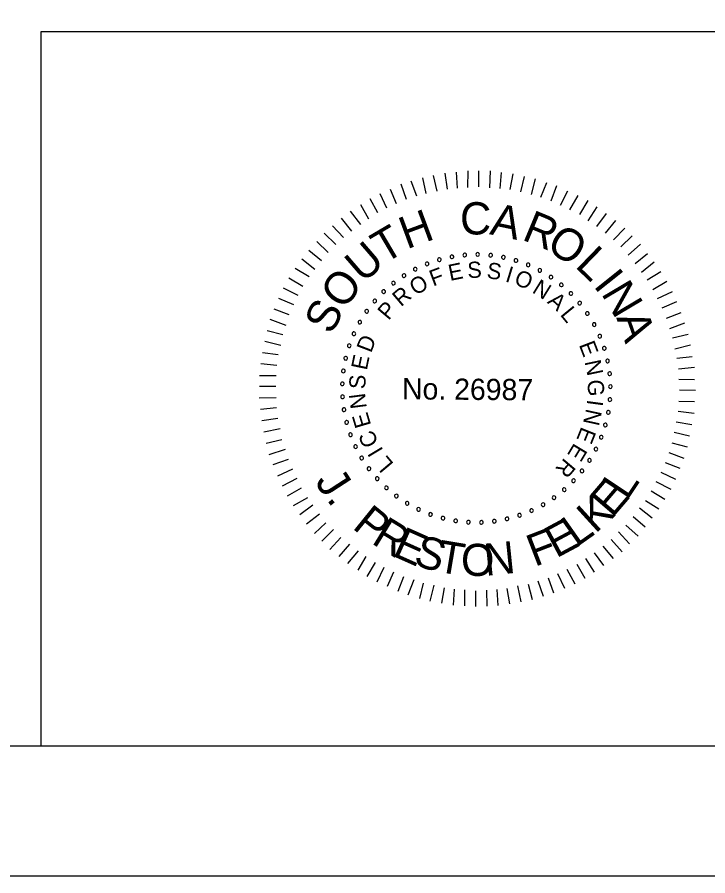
# Model space of a CAD drawing. Extents: x -125.5 to -89.4, y -5.1 to 16.9.
# Drawn here: x -102.992 to -100.335, y -5.066 to -1.761 of the extents above; entities that cross this region are included whole.
import ezdxf

# ---------------------------------------------------------------- set-up
doc = ezdxf.new("R2010")
doc.units = 0
for name, color, linetype in [('BR_BORDER LINES', 7, 'Continuous'), ('BR_TEXT', 7, 'Continuous'), ('Level 31', 7, 'Continuous')]:
    doc.layers.add(name, color=color, linetype=linetype)

msp = doc.modelspace()

# ---------------------------------------------------------------- linework, layer by layer
at = {"layer": 'BR_BORDER LINES'}
for p, q in [((-102.8989, -1.8161), (-97.5337, -1.8161)), ((-102.8989, -4.5661), (-102.8989, -1.8161)), ((-123.6994, -4.5662), (-90.0334, -4.5662))]:
    msp.add_line(p, q, dxfattribs=at)
at = {"layer": 'BR_TEXT'}
for p, q in [((-101.418, -2.4404), (-101.4312, -2.3793)), ((-101.3767, -2.4304), (-101.3908, -2.3711)), ((-101.3372, -2.423), (-101.3461, -2.362)), ((-101.2977, -2.419), (-101.3015, -2.3581)), ((-101.2582, -2.4168), (-101.2576, -2.3524)), ((-101.2161, -2.4146), (-101.2156, -2.3528)), ((-101.1741, -2.4175), (-101.1718, -2.3531)), ((-101.1338, -2.4204), (-101.129, -2.3595)), ((-101.0952, -2.425), (-101.0844, -2.3642)), ((-101.0549, -2.4331), (-101.0407, -2.374)), ((-101.4937, -2.4629), (-101.5147, -2.4044)), ((-101.4541, -2.4504), (-101.476, -2.3927)), ((-101.0138, -2.4437), (-100.9979, -2.3829)), ((-100.977, -2.4543), (-100.9551, -2.397)), ((-100.9376, -2.4675), (-100.9157, -2.4093)), ((-101.5695, -2.4966), (-101.5957, -2.4406)), ((-101.5325, -2.4798), (-101.556, -2.4238)), ((-100.9017, -2.485), (-100.8738, -2.4294)), ((-101.604, -2.5144), (-101.6344, -2.46)), ((-100.8658, -2.5024), (-100.8345, -2.4469)), ((-100.8282, -2.5208), (-100.796, -2.467)), ((-101.6704, -2.5593), (-101.7095, -2.5083)), ((-101.6394, -2.5381), (-101.6698, -2.4838)), ((-100.795, -2.5451), (-100.761, -2.4913)), ((-101.7041, -2.5847), (-101.744, -2.5346)), ((-100.7617, -2.5668), (-100.7252, -2.5165)), ((-100.7293, -2.5928), (-100.6886, -2.5434)), ((-101.7369, -2.6094), (-101.7786, -2.5644)), ((-100.6977, -2.618), (-100.6545, -2.5737)), ((-101.7663, -2.6366), (-101.8106, -2.5925)), ((-100.6697, -2.6456), (-100.6264, -2.6022)), ((-101.7958, -2.6673), (-101.8392, -2.6248)), ((-100.6416, -2.6768), (-100.594, -2.6351)), ((-101.8209, -2.6988), (-101.8704, -2.6598)), ((-100.6144, -2.7088), (-100.5677, -2.6705)), ((-101.8469, -2.732), (-101.8964, -2.6922)), ((-100.5906, -2.7424), (-100.5414, -2.7033)), ((-101.8686, -2.761), (-101.9224, -2.728)), ((-100.5686, -2.7718), (-100.516, -2.7396)), ((-101.893, -2.7977), (-101.9467, -2.7656)), ((-101.9104, -2.8319), (-101.9668, -2.804)), ((-100.5466, -2.8089), (-100.4931, -2.7776)), ((-100.5288, -2.8433), (-100.4711, -2.8164)), ((-101.9279, -2.8687), (-101.9852, -2.8433)), ((-100.5111, -2.8804), (-100.4543, -2.856)), ((-101.9454, -2.9072), (-102.0035, -2.8852)), ((-100.4943, -2.9192), (-100.4374, -2.8982)), ((-101.9577, -2.9474), (-102.0193, -2.9246)), ((-100.4809, -2.9596), (-100.4232, -2.9378)), ((-101.97, -2.9833), (-102.0308, -2.9682)), ((-100.4708, -2.9957), (-100.4107, -2.9816)), ((-101.9772, -3.0253), (-102.0397, -3.0094)), ((-100.4626, -3.0378), (-100.4024, -3.0229)), ((-101.9878, -3.0613), (-102.0487, -3.0531)), ((-100.4543, -3.074), (-100.3951, -3.0667)), ((-101.9925, -3.1024), (-102.0542, -3.0951)), ((-100.4478, -3.1152), (-100.3868, -3.1088)), ((-101.9954, -3.1419), (-102.0597, -3.1414)), ((-100.4464, -3.1547), (-100.3863, -3.1552)), ((-101.9974, -3.183), (-102.06, -3.1825)), ((-100.4442, -3.1959), (-100.3833, -3.1964)), ((-101.9961, -3.226), (-102.0604, -3.2272)), ((-100.4471, -3.2388), (-100.3871, -3.241)), ((-101.9938, -3.2646), (-102.0556, -3.2718)), ((-100.4492, -3.2774), (-100.3883, -3.2856)), ((-101.9898, -3.3058), (-102.0509, -3.3148)), ((-100.4564, -3.3185), (-100.3972, -3.3284)), ((-101.9799, -3.3454), (-102.0426, -3.3586)), ((-100.4653, -3.3579), (-100.4053, -3.3721)), ((-101.9733, -3.3875), (-102.0344, -3.4016)), ((-100.4742, -3.3999), (-100.4143, -3.415)), ((-101.9616, -3.4245), (-102.0236, -3.4454)), ((-100.4848, -3.4367), (-100.4275, -3.4586)), ((-101.95, -3.4632), (-102.0085, -3.4842)), ((-101.9331, -3.5003), (-101.9908, -3.5272)), ((-100.4989, -3.4752), (-100.4424, -3.4971)), ((-100.5163, -3.512), (-100.4599, -3.5399)), ((-101.9162, -3.5364), (-101.9731, -3.566)), ((-100.5346, -3.5479), (-100.4774, -3.5784)), ((-101.8994, -3.5735), (-101.9537, -3.6048)), ((-100.553, -3.5846), (-100.5, -3.6168)), ((-101.8756, -3.6106), (-101.93, -3.6419)), ((-100.5756, -3.6213), (-100.5235, -3.6535)), ((-101.8544, -3.6399), (-101.9045, -3.6764)), ((-100.5981, -3.6503), (-100.5495, -3.6876)), ((-101.829, -3.6736), (-101.8791, -3.7127)), ((-100.6224, -3.6836), (-100.5764, -3.7234)), ((-101.8043, -3.7073), (-101.8485, -3.7481)), ((-101.7754, -3.7333), (-101.8204, -3.7784)), ((-100.6502, -3.7168), (-100.6033, -3.7584)), ((-101.7465, -3.7636), (-101.7889, -3.8095)), ((-100.6787, -3.7423), (-100.6362, -3.7882)), ((-101.714, -3.7895), (-101.7548, -3.8364)), ((-100.7392, -3.7976), (-100.6993, -3.8452)), ((-100.7073, -3.7721), (-100.6648, -3.8188)), ((-101.6808, -3.8156), (-101.7207, -3.8633)), ((-100.772, -3.8231), (-100.7364, -3.8714)), ((-101.6501, -3.8373), (-101.6814, -3.8894)), ((-101.6151, -3.8599), (-101.6464, -3.9137)), ((-100.8393, -3.8663), (-100.808, -3.9206)), ((-100.8057, -3.8443), (-100.7727, -3.8969)), ((-101.5809, -3.8799), (-101.608, -3.9355)), ((-101.5442, -3.8974), (-101.5687, -3.953)), ((-100.8773, -3.8857), (-100.8468, -3.9418)), ((-101.5057, -3.9149), (-101.5276, -3.9713)), ((-101.4663, -3.9272), (-101.4891, -3.9854)), ((-100.9892, -3.9311), (-100.9682, -3.9897)), ((-100.9496, -3.9194), (-100.9286, -3.9763)), ((-100.9135, -3.9026), (-100.8865, -3.9586)), ((-101.4304, -3.9395), (-101.4446, -3.9986)), ((-101.3892, -3.9467), (-101.4044, -4.0084)), ((-101.3499, -3.9582), (-101.3598, -4.0165)), ((-101.3104, -3.9628), (-101.3152, -4.0246)), ((-101.271, -3.9657), (-101.2715, -4.0275)), ((-101.1466, -3.9642), (-101.1428, -4.026)), ((-101.1079, -3.9602), (-101.098, -4.0186)), ((-101.0675, -3.9494), (-101.0542, -4.0113)), ((-101.0262, -3.9429), (-101.0112, -4.0022)), ((-101.229, -3.9686), (-101.2295, -4.0296)), ((-101.1869, -3.9664), (-101.1857, -4.0282))]:
    msp.add_line(p, q, dxfattribs=at)
for centre, start, end in [((-101.3196, -2.6831), 10.6038, 190.6038), ((-101.2702, -2.6764), 5.0653, 185.0653), ((-101.2702, -2.6764), 185.0653, 5.0653), ((-101.2204, -2.6745), 359.5268, 179.5268), ((-101.2204, -2.6745), 179.5268, 359.5268), ((-101.1707, -2.6774), 173.9884, 353.9884), ((-101.1707, -2.6774), 353.9884, 173.9884), ((-101.4153, -2.7106), 21.6807, 201.6807), ((-101.4153, -2.7106), 201.6807, 21.6807), ((-101.3681, -2.6945), 16.1422, 196.1422), ((-101.3681, -2.6945), 196.1422, 16.1422), ((-101.3196, -2.6831), 190.6038, 10.6038), ((-101.1214, -2.6851), 168.4499, 348.4499), ((-101.1214, -2.6851), 348.4499, 168.4499), ((-101.0732, -2.6976), 162.9114, 342.9114), ((-101.0732, -2.6976), 342.9114, 162.9114), ((-101.0263, -2.7146), 337.373, 157.373), ((-101.4607, -2.7311), 27.2191, 207.2191), ((-101.4607, -2.7311), 207.2191, 27.2191), ((-101.0263, -2.7146), 157.373, 337.373), ((-100.9814, -2.736), 151.8345, 331.8345), ((-100.9814, -2.736), 331.8345, 151.8345), ((-101.5039, -2.7559), 32.7576, 212.7576), ((-101.5039, -2.7559), 212.7576, 32.7576), ((-100.9387, -2.7617), 146.2961, 326.2961), ((-100.9387, -2.7617), 326.2961, 146.2961), ((-101.5445, -2.7848), 38.2961, 218.2961), ((-101.5445, -2.7848), 218.2961, 38.2961), ((-100.8987, -2.7914), 140.7576, 320.7576), ((-100.8987, -2.7914), 320.7576, 140.7576), ((-101.5821, -2.8175), 43.8345, 223.8345), ((-101.5821, -2.8175), 223.8345, 43.8345), ((-100.8617, -2.8249), 135.2191, 315.2191), ((-100.8617, -2.8249), 315.2191, 135.2191), ((-101.6164, -2.8536), 49.373, 229.373), ((-101.6164, -2.8536), 229.373, 49.373), ((-100.8282, -2.8617), 129.6807, 309.6807), ((-100.8282, -2.8617), 309.6807, 129.6807), ((-101.6471, -2.8929), 54.9114, 234.9114), ((-101.6471, -2.8929), 234.9114, 54.9114), ((-100.7983, -2.9016), 124.1422, 304.1422), ((-100.7983, -2.9016), 304.1422, 124.1422), ((-101.6738, -2.935), 60.4499, 240.4499), ((-101.6738, -2.935), 240.4499, 60.4499), ((-100.7724, -2.9442), 118.6038, 298.6038), ((-100.7724, -2.9442), 298.6038, 118.6038), ((-101.6964, -2.9794), 65.9884, 245.9884), ((-101.6964, -2.9794), 245.9884, 65.9884), ((-100.7508, -2.9891), 113.0653, 293.0653), ((-100.7508, -2.9891), 293.0653, 113.0653), ((-101.7145, -3.0258), 71.5268, 251.5268), ((-101.7145, -3.0258), 251.5268, 71.5268), ((-100.7336, -3.0359), 107.5268, 287.5268), ((-100.7336, -3.0359), 287.5268, 107.5268), ((-101.7281, -3.0738), 77.0653, 257.0653), ((-101.7281, -3.0738), 257.0653, 77.0653), ((-100.721, -3.0841), 101.9884, 281.9884), ((-100.721, -3.0841), 281.9884, 101.9884), ((-101.737, -3.1228), 82.6038, 262.6038), ((-101.737, -3.1228), 262.6038, 82.6038), ((-100.7131, -3.1333), 96.4499, 276.4499), ((-100.7131, -3.1333), 276.4499, 96.4499), ((-101.7411, -3.1724), 88.1422, 268.1422), ((-101.7411, -3.1724), 268.1422, 88.1422), ((-100.71, -3.183), 90.9114, 270.9114), ((-100.71, -3.183), 270.9114, 90.9114), ((-101.7404, -3.2223), 93.6807, 273.6807), ((-101.7404, -3.2223), 273.6807, 93.6807), ((-100.7118, -3.2328), 85.373, 265.373), ((-100.7118, -3.2328), 265.373, 85.373), ((-101.7349, -3.2718), 99.2191, 279.2191), ((-101.7349, -3.2718), 279.2191, 99.2191), ((-100.7183, -3.2822), 79.8345, 259.8345), ((-100.7183, -3.2822), 259.8345, 79.8345), ((-101.7246, -3.3206), 104.7576, 284.7576), ((-101.7246, -3.3206), 284.7576, 104.7576), ((-100.7295, -3.3308), 74.2961, 254.2961), ((-100.7295, -3.3308), 254.2961, 74.2961), ((-101.7097, -3.3681), 110.2961, 290.2961), ((-101.7097, -3.3681), 290.2961, 110.2961), ((-100.7454, -3.378), 68.7576, 248.7576), ((-100.7454, -3.378), 248.7576, 68.7576), ((-101.6903, -3.414), 115.8345, 295.8345), ((-101.6903, -3.414), 295.8345, 115.8345), ((-100.7658, -3.4235), 63.2191, 243.2191), ((-100.7658, -3.4235), 243.2191, 63.2191), ((-101.6665, -3.4578), 121.373, 301.373), ((-101.6665, -3.4578), 301.373, 121.373), ((-100.7904, -3.4668), 57.6807, 237.6807), ((-100.7904, -3.4668), 237.6807, 57.6807), ((-101.6386, -3.4991), 126.9114, 306.9114), ((-101.6386, -3.4991), 306.9114, 126.9114), ((-100.8192, -3.5075), 52.1422, 232.1422), ((-100.8192, -3.5075), 232.1422, 52.1422), ((-101.6069, -3.5375), 132.4499, 312.4499), ((-101.6069, -3.5375), 312.4499, 132.4499), ((-101.5716, -3.5727), 137.9884, 317.9884), ((-101.5716, -3.5727), 317.9884, 137.9884), ((-100.8517, -3.5452), 46.6038, 226.6038), ((-100.8517, -3.5452), 226.6038, 46.6038), ((-101.5331, -3.6043), 143.5268, 323.5268), ((-101.5331, -3.6043), 323.5268, 143.5268), ((-100.8877, -3.5797), 41.0653, 221.0653), ((-100.8877, -3.5797), 221.0653, 41.0653), ((-101.4917, -3.632), 149.0653, 329.0653), ((-101.4917, -3.632), 329.0653, 149.0653), ((-100.9688, -3.6374), 29.9884, 209.9884), ((-100.9688, -3.6374), 209.9884, 29.9884), ((-100.9269, -3.6105), 35.5268, 215.5268), ((-100.9269, -3.6105), 215.5268, 35.5268), ((-101.4478, -3.6556), 154.6038, 334.6038), ((-101.4478, -3.6556), 334.6038, 154.6038), ((-101.4018, -3.6749), 340.1422, 160.1422), ((-101.0132, -3.6601), 24.4499, 204.4499), ((-101.0132, -3.6601), 204.4499, 24.4499), ((-101.4018, -3.6749), 160.1422, 340.1422), ((-101.3542, -3.6896), 165.6807, 345.6807), ((-101.3542, -3.6896), 345.6807, 165.6807), ((-101.3054, -3.6997), 351.2191, 171.2191), ((-101.3054, -3.6997), 171.2191, 351.2191), ((-101.2559, -3.705), 356.7576, 176.7576), ((-101.2061, -3.7055), 2.2961, 182.2961), ((-101.1564, -3.7012), 7.8345, 187.8345), ((-101.1564, -3.7012), 187.8345, 7.8345), ((-101.1074, -3.6921), 13.373, 193.373), ((-101.1074, -3.6921), 193.373, 13.373), ((-101.0595, -3.6784), 18.9114, 198.9114), ((-101.0595, -3.6784), 198.9114, 18.9114), ((-101.2559, -3.705), 176.7576, 356.7576), ((-101.2061, -3.7055), 182.2961, 2.2961)]:
    msp.add_arc(centre, 0.00701, start, end, dxfattribs=at)
at = {"layer": 'Level 31'}
msp.add_lwpolyline([(-125.5328, -5.0661), (-89.5328, -5.0661), (-89.5328, 16.9339), (-125.5328, 16.9339)], close=True, dxfattribs=at)

# ---------------------------------------------------------------- texts
at = {"layer": 'BR_TEXT'}
for s, height, rotation, p in [('C', 0.1241, 359.5482, (-101.2889, -2.5969)), ('H', 0.1241, 20.3637, (-101.4933, -2.6552)), ('A', 0.1241, 348.1981, (-101.1775, -2.5961)), ('R', 0.1241, 337.4344, (-101.0542, -2.616)), ('T', 0.1241, 30.4992, (-101.5812, -2.7128)), ('O', 0.1239, 326.5869, (-100.962, -2.6528)), ('U', 0.1241, 40.8022, (-101.6624, -2.7875)), ('L', 0.1241, 315.9488, (-100.8494, -2.7205)), ('E', 0.0622, 11.4103, (-101.3269, -2.7764)), ('S', 0.0622, 2.208, (-101.2591, -2.7654)), ('S', 0.0622, 352.6608, (-101.1878, -2.7657)), ('O', 0.1241, 52.0267, (-101.7369, -2.8914)), ('F', 0.0622, 20.6127, (-101.392, -2.7981)), ('I', 0.0622, 343.1136, (-101.1175, -2.7777)), ('O', 0.0622, 338.4392, (-101.0841, -2.7878)), ('I', 0.1241, 308.6613, (-100.778, -2.7948)), ('O', 0.0622, 30.8477, (-101.4594, -2.8341)), ('N', 0.0622, 328.2042, (-101.0145, -2.8192)), ('N', 0.1241, 300.7037, (-100.7474, -2.8242)), ('R', 0.0622, 40.3949, (-101.5156, -2.878)), ('A', 0.0622, 318.657, (-100.9555, -2.8592)), ('S', 0.1239, 63.2511, (-101.7823, -2.9871)), ('P', 0.0622, 49.9421, (-101.5636, -2.9306)), ('L', 0.0622, 309.4546, (-100.9057, -2.9066)), ('A', 0.1241, 289.4792, (-100.6882, -2.9172)), ('D', 0.0622, 69.0364, (-101.6306, -3.0559)), ('E', 0.0622, 291.049, (-100.8319, -3.0219)), ('E', 0.0622, 78.2388, (-101.6472, -3.1226)), ('N', 0.0622, 281.8466, (-100.8097, -3.0869)), ('S', 0.0622, 87.786, (-101.6529, -3.1936)), ('No. 26987', 0.08175, 359.5268, (-101.5118, -3.232)), ('G', 0.0622, 272.2995, (-100.7979, -3.1572)), ('N', 0.0622, 97.3332, (-101.6467, -3.2646)), ('I', 0.0622, 262.4084, (-100.7983, -3.231)), ('E', 0.0622, 106.5355, (-101.6297, -3.3312)), ('N', 0.0622, 257.7339, (-100.8028, -3.2656)), ('C', 0.0622, 116.4266, (-101.5998, -3.3987)), ('E', 0.0622, 248.1867, (-100.8209, -3.3346)), ('E', 0.0622, 238.9844, (-100.8488, -3.3973)), ('I', 0.0622, 121.1011, (-101.5818, -3.4285)), ('L', 0.0622, 129.9595, (-101.5411, -3.4807)), ('R', 0.0622, 229.782, (-100.8865, -3.4548)), ('J', 0.1236, 302.9559, (-101.849, -3.5492)), ('E', 0.1236, 49.3639, (-100.703, -3.6911)), ('L', 0.1236, 56.4247, (-100.6455, -3.6233)), ('K', 0.1236, 42.3031, (-100.7683, -3.7512)), ('.', 0.1236, 309.3974, (-101.8049, -3.6172)), ('P', 0.1236, 321.1035, (-101.7065, -3.7264)), ('R', 0.1236, 328.5359, (-101.6332, -3.7844)), ('E', 0.1236, 28.1814, (-100.9186, -3.8452)), ('L', 0.1236, 35.2422, (-100.8406, -3.8028)), ('E', 0.1236, 335.9684, (-101.5531, -3.8325)), ('F', 0.1236, 21.1206, (-101.0013, -3.8776)), ('S', 0.1236, 343.0292, (-101.4718, -3.8682)), ('T', 0.1236, 350.4617, (-101.3821, -3.8947)), ('O', 0.1236, 358.1419, (-101.2867, -3.9097)), ('N', 0.1236, 5.8221, (-101.1902, -3.9118))]:
    msp.add_text(s, height=height, rotation=rotation, dxfattribs=at).set_placement(p)

doc.saveas('drawing.dxf')
